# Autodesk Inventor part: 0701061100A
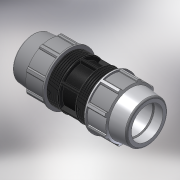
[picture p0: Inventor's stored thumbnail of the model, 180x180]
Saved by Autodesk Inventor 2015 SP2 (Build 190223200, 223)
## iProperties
Created: 2017-02
Part Number: 0701061100A
Material: Generic
Description: PLASSON COUPLER 110-110
Document SubType Name: Modeling
Designer: KIM
Mass: 3885.53 g
Surface Area: 4713.66 cm^2
Volume: 3885.53 cm^3
Density: 1 g/cm^3
Appearance: Default
Author: KIM
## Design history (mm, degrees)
derived "87010.ipt"
feature "Solid1::87010.ipt"
tag "TaggingFeature1"
body "Solid1"
other parameters: "d1" = 393, "d4" = 32.75, "d5" = 56.14286, "d7" = 181, "d8" = 135.75, "d9" = 56.14286, "d11" = 5.61429, "d12" = 144.8, "d13" = 120 deg, "d14" = 143, "d15" = 6 deg, "d16" = 162.9, "d18" = 5.5, "d19" = 35 deg, "d20" = 17.5 deg, "d21" = 168.33, "d23" = 0, "d25" = 360 deg, "d27" = 3.62, "d33" = 2.2, "d34" = 9.05, "d36" = 0, "d37" = 2.2, "d38" = 2.2, "d40" = 360 deg, "d42" = 70.74, "d46" = 3.3, "d50" = 4.9125, "d51" = 0, "d53" = 3.59314, "d54" = 3.59314, "d57" = 7.18629, "d62" = 159.642, "d64" = 99, "d65" = 194, "E_" = 181, "H_" = 393, "l_" = 194, "d52" = 35.93143
